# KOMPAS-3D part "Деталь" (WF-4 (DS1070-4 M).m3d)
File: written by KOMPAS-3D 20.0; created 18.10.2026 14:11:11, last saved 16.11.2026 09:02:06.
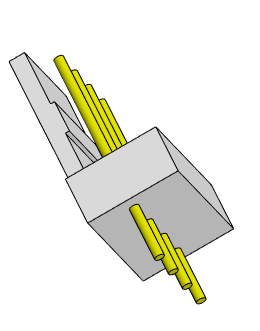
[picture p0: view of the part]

Document properties: Полное имя файла: D:\RicWork\Project-EPS32\box_compas\разъемы\WF-4 (DS1070-4 M).m3d

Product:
- Part/product: Деталь
    Масса: 0.00202132

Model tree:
1. Эскиз:1
2. Элемент выдавливания:1
     Расстояние 1 = 10.16
3. Эскиз:2  (with: Элемент выдавливания:1)
4. Элемент выдавливания:2
     Расстояние 2 = 1.27
5. Эскиз:3  (with: Элемент выдавливания:1)
6. Элемент выдавливания:3
     Расстояние 2 = 1.27
7. Эскиз:4  (with: Элемент выдавливания:1)
8. Элемент выдавливания:4
     Расстояние 1 = 3.4
9. Массив по сетке:1  (with: Элемент выдавливания:4, Эскиз:4)  (4 pattern instances)
     Шаг 1 = 2.54; Угол раствора = 90
10. Эскиз:5  (with: Элемент выдавливания:1, Элемент выдавливания:4, Элемент выдавливания:2, Элемент выдавливания:3)
11. Элемент выдавливания:5
     Расстояние 1 = 7.15
12. Массив по сетке:3  (with: Элемент выдавливания:5, Эскиз:5, Элемент выдавливания:1)  (4 pattern instances)
     Шаг 1 = 2.54; Угол раствора = 90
